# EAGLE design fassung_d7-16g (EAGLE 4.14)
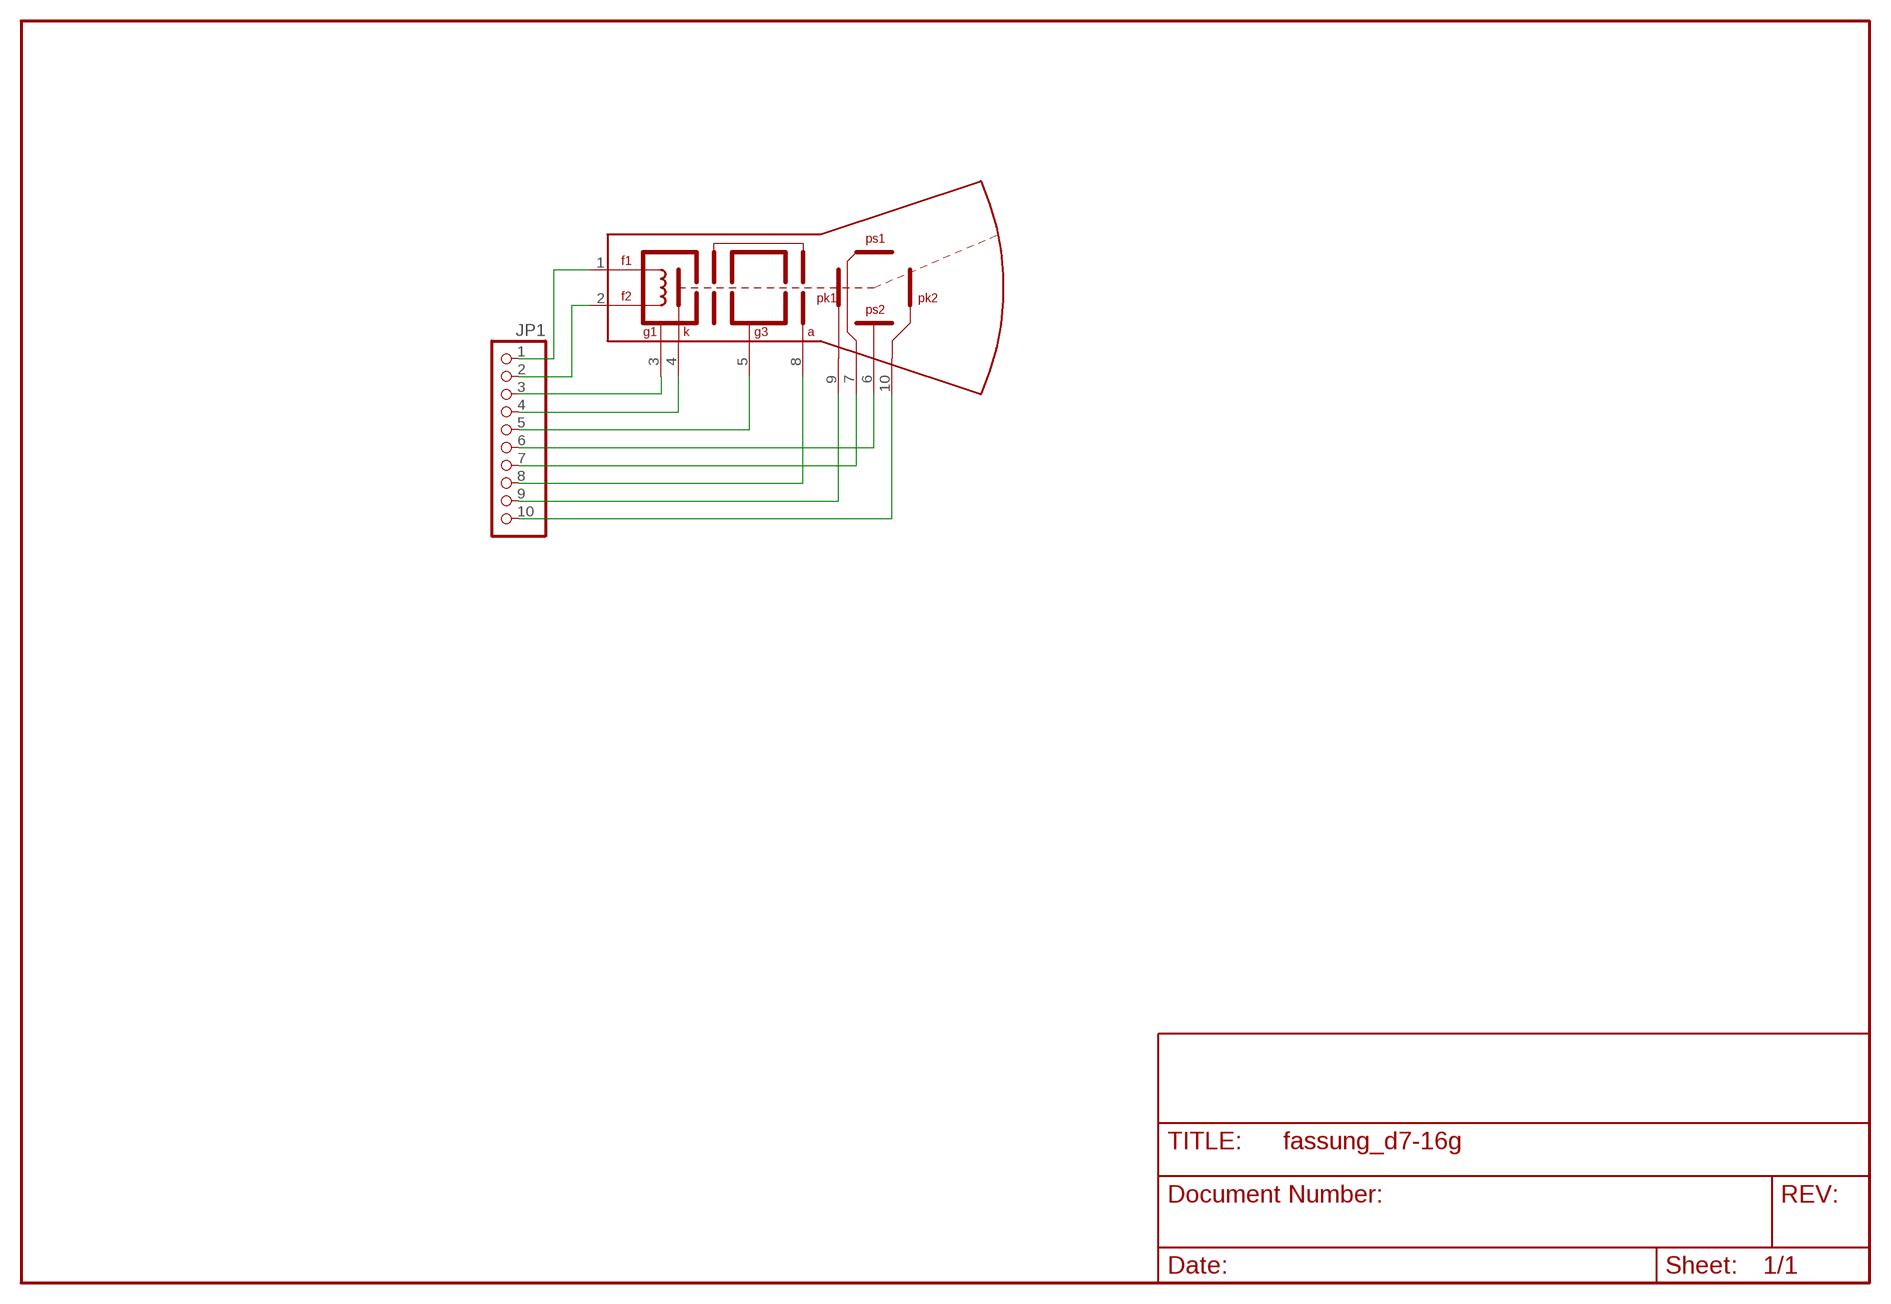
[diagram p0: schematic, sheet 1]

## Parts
JP1  PINHD-1X10  [1X10]
RÖ1  D7-16GJ  [D7-16GJ]

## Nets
A: JP1.8 RÖ1.8(A)
F1: JP1.1 RÖ1.1(F1)
F2: JP1.2 RÖ1.2(F2)
G1: JP1.3 RÖ1.3(G1)
G3: JP1.5 RÖ1.5(G3)
K: JP1.4 RÖ1.4(K)
PK1: JP1.9 RÖ1.9(PK1)
PK2: JP1.10 RÖ1.10(PK2)
PS1: JP1.7 RÖ1.7(PS1)
PS2: JP1.6 RÖ1.6(PS2)

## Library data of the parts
JP1 = pinhead:PINHD-1X10: PIN HEADER
RÖ1 = eigene:D7-16GJ: Kathodenstrahlröhre D7-16G

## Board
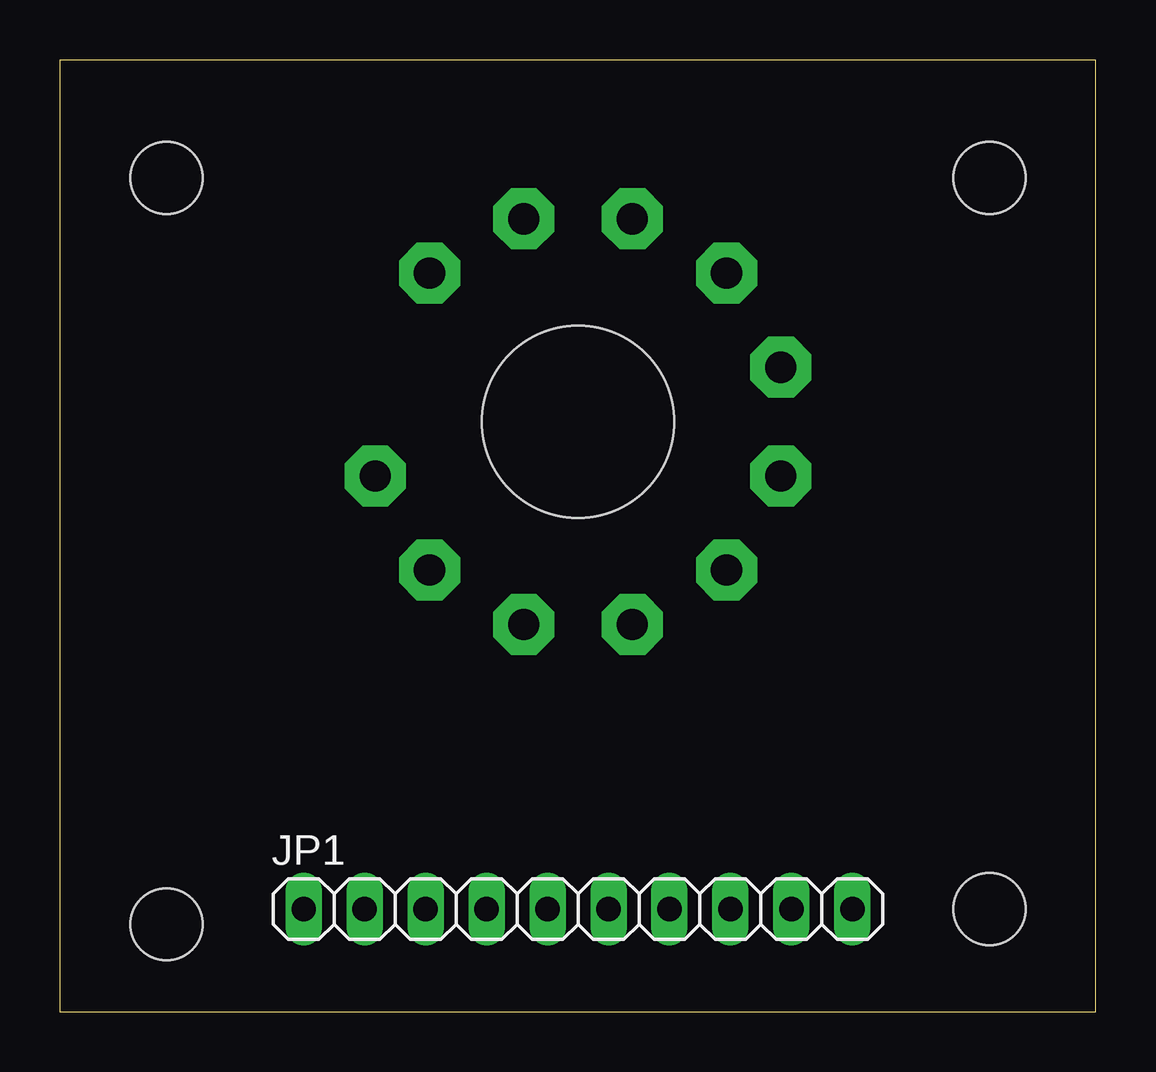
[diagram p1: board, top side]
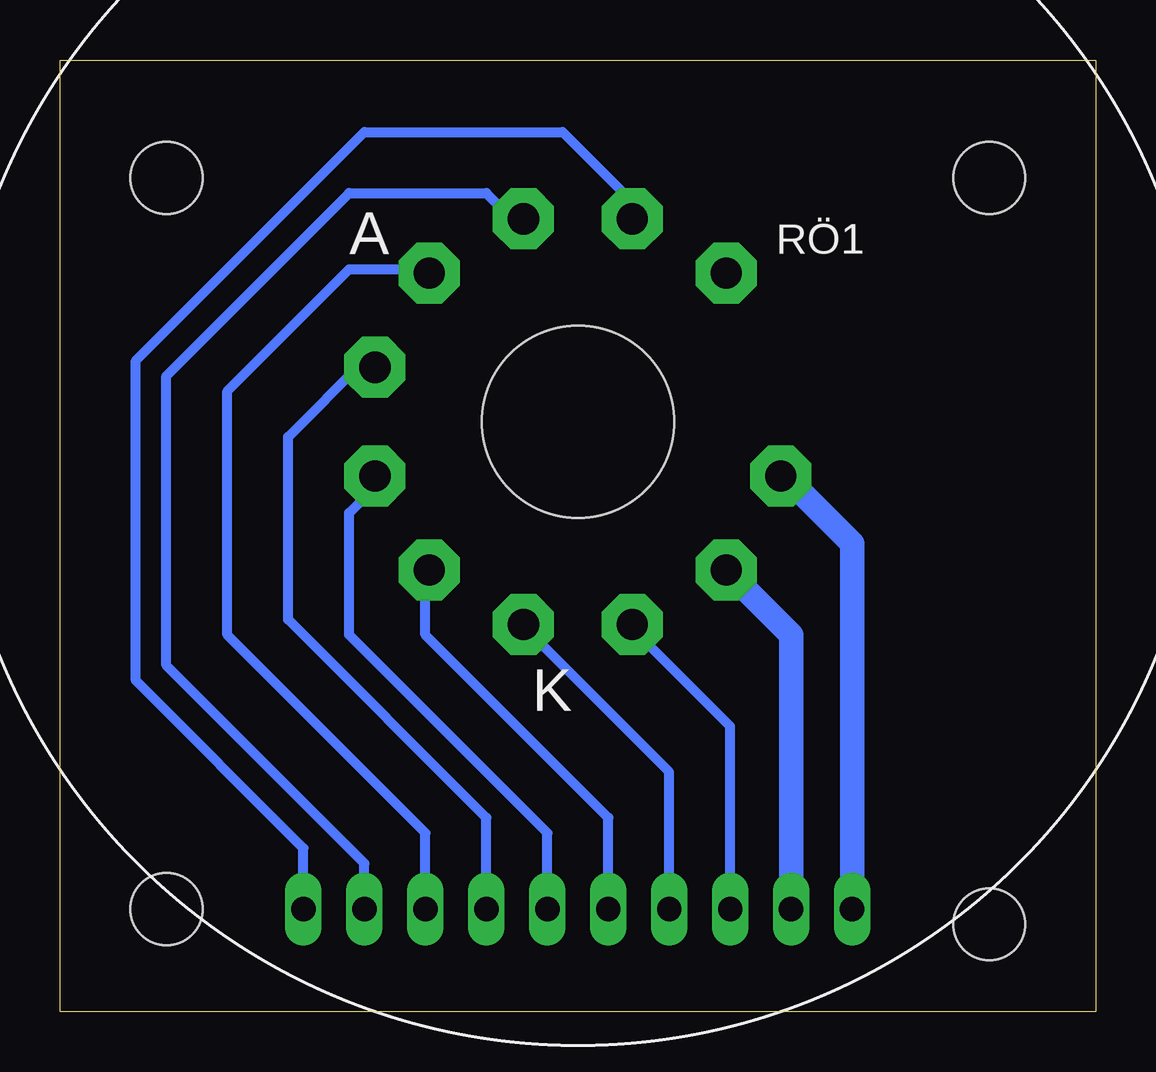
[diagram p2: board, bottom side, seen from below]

Size 43.16 x 39.68 mm. Coordinates in mm from the lower left corner, seen from the top.
Outline: 0,0 43.16,0 43.16,39.68 0,39.68 0,0
Copper layers (1+16): Top 0.035mm / dielectric 1.5mm / Bottom 0.035mm
Design rules "default": minimum track width 10mil, minimum drill 24mil, track to track 8mil, track to pad 8mil, pad to pad 8mil, via to via 8mil, smd to smd 8mil, copper to edge 40mil, drill to drill 8mil, minimum pad ring 10mil, minimum via ring 8mil, stop-mask expansion 4mil, vias tented up to drill 0mil, thermal gap 10mil

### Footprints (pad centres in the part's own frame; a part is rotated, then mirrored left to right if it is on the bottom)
1X10 = drill 1.016 long: 1 -11.43,0; 2 -8.89,0; 3 -6.35,0; 4 -3.81,0; 5 -1.27,0; 6 1.27,0; 7 3.81,0; 8 6.35,0; 9 8.89,0; 10 11.43,0
D7-16GJ = drill 1.3 pad 2.54 octagon: 1 8.452,-2.265; 2 6.187,-6.187; 3 2.265,-8.452; 4 -2.265,-8.452; 5 -6.187,-6.187; 6 -8.452,-2.265; 7 -8.452,2.265; 8 -6.187,6.187; 9 -2.265,8.452; 10 2.265,8.452; 11 6.187,6.187 | hole 8: 0,0
BOHRUNG_3MM = hole 3: 0,0

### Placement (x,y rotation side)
JP1  21.59,4.28 0 top
RÖ1  21.59,24.6 0 bottom
U$1  [BOHRUNG_3MM]  4.44,34.76 0 top
U$2  [BOHRUNG_3MM]  38.73,34.76 0 top
U$3  [BOHRUNG_3MM]  4.44,3.65 0 top
U$4  [BOHRUNG_3MM]  38.73,4.28 0 top

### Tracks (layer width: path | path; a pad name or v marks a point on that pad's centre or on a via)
A
  Bottom 0.406: JP1.8 27.93,7.46 36.19,15.71 36.19,25.87 31.11,30.95 27.93,30.95 RÖ1.8
F1
  Bottom 1.016: JP1.1 10.15,19.52 13.13,22.5 | 13.33,22.7 13.13,22.5 | 13.13,22.5 RÖ1.1
F2
  Bottom 1.016: JP1.2 12.7,15.71 RÖ1.2
G1
  Bottom 0.406: RÖ1.3 19.24,16.15 19.05,15.71 15.23,11.9 JP1.3
G3
  Bottom 0.406: JP1.5 20.32,8.09 27.93,15.71 27.93,18.25 RÖ1.5
K
  Bottom 0.406: JP1.4 17.78,10 23.49,15.71 23.69,16.15 | 23.49,16.35 23.69,16.15 | 23.69,16.15 RÖ1.4
PK1
  Bottom 0.406: JP1.9 30.48,6.18 38.73,14.44 38.73,26.51 31.11,34.12 25.39,34.12 24.12,32.86 23.93,33.05 RÖ1.9
PK2
  Bottom 0.406: JP1.10 33.02,6.82 40,13.81 40,27.14 30.48,36.66 22.22,36.66 19.05,33.49 19.48,33.05 | 19.68,32.86 19.48,33.05 | 19.48,33.05 RÖ1.10
PS1
  Bottom 0.406: JP1.7 25.39,8.09 33.65,16.35 33.65,23.96 30.48,27.14 29.84,27.14 30.04,26.94 RÖ1.7
PS2
  Bottom 0.406: JP1.6 22.86,7.46 31.11,15.71 31.11,20.79 29.84,22.06 30.04,22.26 RÖ1.6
